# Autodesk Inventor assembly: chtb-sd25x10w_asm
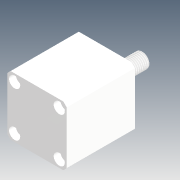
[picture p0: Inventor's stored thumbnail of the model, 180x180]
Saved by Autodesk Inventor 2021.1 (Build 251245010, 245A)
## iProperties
Company: Microsoft
Created: 2018-05
Part Number: chtb-sd25x10w_asm
Description: STEP AP214
Document SubType Name: Assembly
Designer: user
Title: chtb-sd25x10w_asm.STEP
Author: Windows
Revision Number: ÈÎºÎ
Sending System: SolidWorks 2015
Preprocessor: SwSTEP 2.0
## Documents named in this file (4)
- D:\Vault_2016\Projekty\Clamptek\Hydraulic\CHTB\CHTB-25\Inventor\chtb-sd25x10w\chtb-sd25x10w_asm.iam
- D:\Vault_2016\Projekty\Clamptek\Hydraulic\CHTB\CHTB-25\Inventor\chtb-sd25x10w\CHTB-25QG.ipt
- D:\Vault_2016\Projekty\Clamptek\Hydraulic\CHTB\CHTB-25\Inventor\chtb-sd25x10w\CHTB-SD25X10NBT.ipt
- D:\Vault_2016\Projekty\Clamptek\Hydraulic\CHTB\CHTB-25\Inventor\chtb-sd25x10w\CHTB-SD25X10WHSG.ipt
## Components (3 placed, 3 different names)
1. CHTB-25QG_1
2. CHTB-SD25X10NBT_2
3. CHTB-SD25X10WHSG_3
